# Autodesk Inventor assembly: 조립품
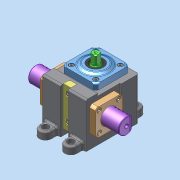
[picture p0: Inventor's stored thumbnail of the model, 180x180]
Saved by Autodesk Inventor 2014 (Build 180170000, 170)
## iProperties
Created: 2024-11
Part Number: 조립품
Document SubType Name: Assembly
Designer: dg
Author: dg
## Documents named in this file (10)
- C:\Users\dg\Desktop\741104V1008\조립품.iam
- C:\Users\dg\Desktop\741104V1008\본체.ipt
- C:\Users\dg\Documents\Inventor\피니언 축.ipt
- C:\Users\dg\Desktop\741104V1008\가져온 구성요소\깊음 홈 볼 베어링 6202\깊음 홈 볼 베어링 6202.ipt
- C:\Users\dg\Desktop\741104V1008\가져온 구성요소\커버\커버.ipt
- C:\Users\dg\Desktop\741104V1008\가져온 구성요소\오일 실 15 25 4\오일 실 15 25 4.ipt
- C:\Users\dg\Desktop\741104V1008\가져온 구성요소\육각 소켓 머리 볼트 M4x10\육각 소켓 머리 볼트 M4x10.ipt
- C:\Users\dg\Desktop\741104V1008\가져온 구성요소\수지 부시\수지 부시.ipt
- C:\Users\dg\Desktop\741104V1008\가져온 구성요소\래크\래크.ipt
- C:\Users\dg\Desktop\741104V1008\가져온 구성요소\스톱퍼\스톱퍼.ipt
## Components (1 placed, 1 different names)
1. 피니언 축:1
